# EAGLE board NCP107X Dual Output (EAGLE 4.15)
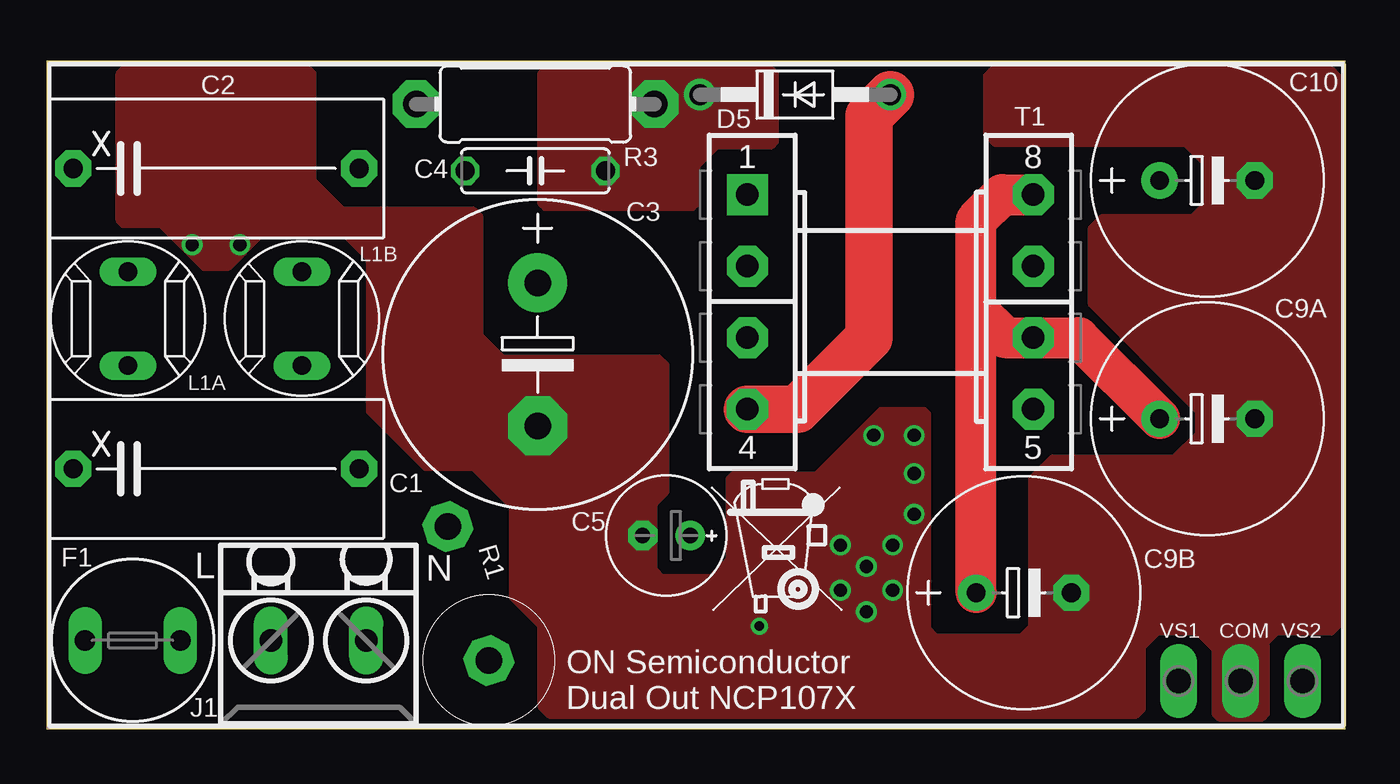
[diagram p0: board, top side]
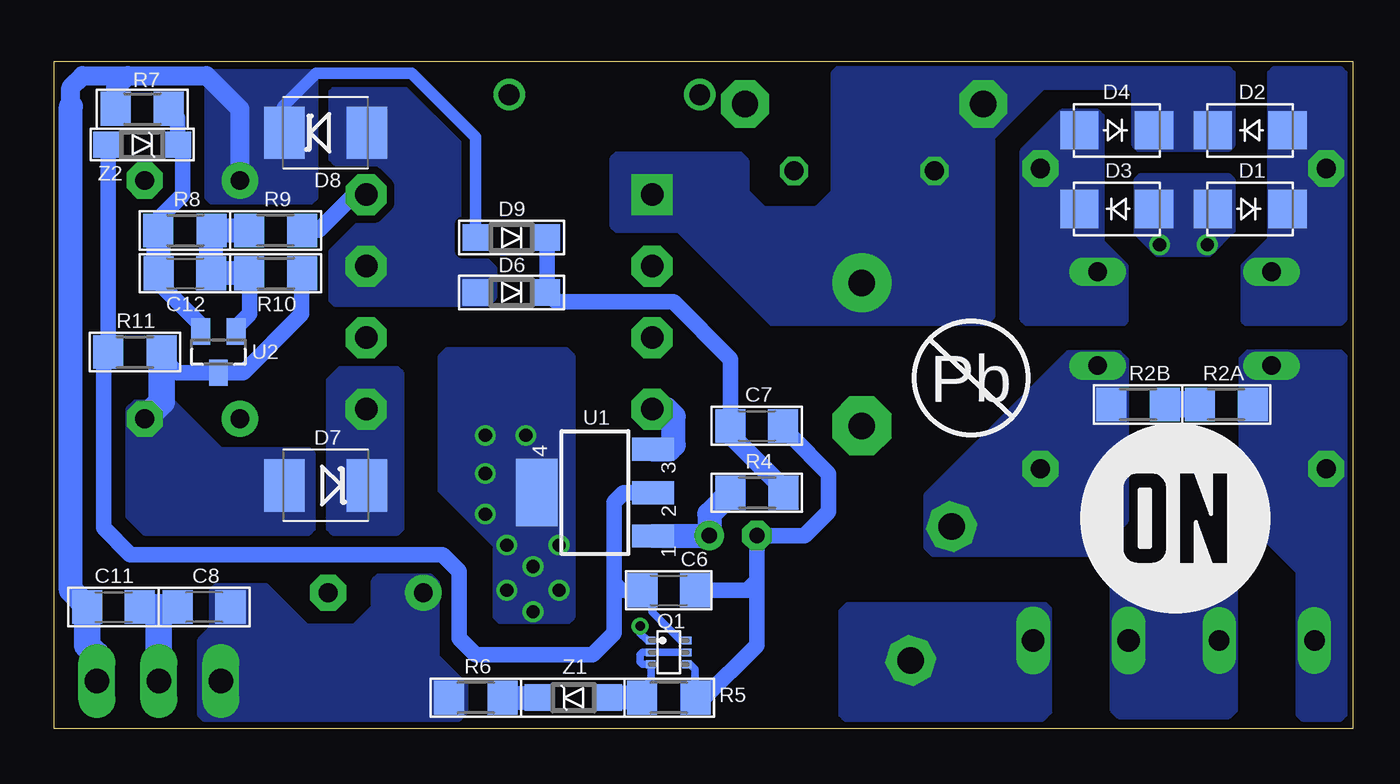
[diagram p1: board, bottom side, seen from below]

Size 69.22 x 35.56 mm. Coordinates in mm from the lower left corner, seen from the top.
Outline: 0,0 69.22,0 69.22,35.56 0,35.56 0,0
Copper layers (1*16): Top 0.035mm / dielectric 1.5mm / Bottom 0.035mm
Design rules "default": minimum track width 10mil, minimum drill 19mil, track to track 8mil, track to pad 8mil, pad to pad 8mil, via to via 8mil, smd to smd 8mil, copper to edge 10mil, drill to drill 8mil, minimum pad ring 10mil, minimum via ring 8mil, stop-mask expansion 4mil, vias tented up to drill 0mil, thermal gap 10mil

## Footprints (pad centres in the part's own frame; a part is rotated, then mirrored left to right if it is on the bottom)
XC18B7.5LS15 = drill 1.016 pad 1.93 octagon: 1 -7.62,0; 2 7.62,0
E7,5-16 = drill 1.4 pad 3.15 round: + -3.81,0 | drill 1.4 pad 3.15 octagon: - 3.81,0
C075-025X080 = drill 1 octagon: 1 -3.74,0; 2 3.74,0
E2.5-6.5 = drill 0.813 pad 1.575 round: + -1.27,0 | drill 0.813 pad 1.575 octagon: - 1.27,0
C1206 = smd 1.6 x 1.8: 1 -1.4,0; 2 1.4,0
E5-12,5 = drill 1 pad 1.93 round: + -2.54,0 | drill 1 pad 1.93 octagon: - 2.54,0
P1-13Y = drill 1.321 pad 1.905 long: 1 0,0
SMA-DIODE = smd 2.032 x 2.032: A 1.994,0; C -1.994,0
DO41-10 = drill 1.118 round: A 5.08,0; C -5.08,0
SOD123 = smd 1.4 x 1.4: A 1.9,0; C -1.9,0
SMB@1 = smd 2.159 x 2.794: A 2.2,0; C -2.2,0
TR5 = drill 1.1 pad 1.778 long: 1 -2.54,0; 2 2.54,0
2-PIN = drill 1.2 long: + -2.54,0; - 2.54,0
WE-7447728215 = drill 1 long: P$1 -2.5,0; P$2 2.5,0
SOT-363/SC-88 = smd 0.508 x 0.406: 1 -0.95,0.635; 2 -0.95,0; 3 -0.95,-0.635; 4 0.95,-0.635; 5 0.95,0; 6 0.95,0.635
3W-STAND-UP = drill 1.4 pad 2.54 octagon: P$1 3.75,0; P$2 -3.71,0
R1206 = smd 1.6 x 1.803: 1 -1.422,0; 2 1.422,0
0411/12 = drill 1.4 pad 2.54 octagon: 1 -6.35,0; 2 6.35,0
E_16/8/5-EF_16-HORIZONTAL = drill 1.2 pad 2.184 square: 1 -7.62,5.715 | drill 1.2 pad 2.184 octagon: 2 -7.62,1.905; 3 -7.62,-1.905; 4 -7.62,-5.715; 5 7.62,-5.715; 6 7.62,-1.905; 7 7.62,1.905; 8 7.62,5.715
SOT-223 = smd 1.219 x 2.235: 1 -2.311,-3.099; 2 0,-3.099; 3 2.311,-3.099 | smd 3.6 x 2.2: 4 0,3.099
SOT-23 = smd 1 x 1.4: 1 -0.95,-1.1; 2 0.95,-1.1; 3 0,1.1

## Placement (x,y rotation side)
C1  100nF  [XC18B7.5LS15]  9.02,13.84 0 top
C2  100nF  [XC18B7.5LS15]  9.02,29.85 0 top
C3  10uF  [E7,5-16]  26.16,19.94 270 top
C4  1nF  [C075-025X080]  26.04,29.72 0 top
C5  22uF  [E2.5-6.5]  33.02,10.29 180 top
C6  1nF  [C1206]  36.45,7.37 0 bottom
C7  0.1uF  [C1206]  31.75,16.13 0 bottom
C8  0.1uF  [C1206]  61.21,6.48 180 bottom
C9A  1500uF  [E5-12,5]  61.85,16.51 0 top
C9B  1500uF  [E5-12,5]  52.07,7.24 0 top
C10  1000uF  [E5-12,5]  61.85,29.21 0 top
C11  0.1uF  [C1206]  66.04,6.48 0 bottom
C12  0.1uF  [C1206]  62.23,24.26 0 bottom
COM  TPPAD1-13Y  [P1-13Y]  63.63,2.54 0 top
D1  MRA4007  [SMA-DIODE]  5.46,27.69 180 bottom
D2  MRA4007  [SMA-DIODE]  5.46,31.88 0 bottom
D3  MRA4007  [SMA-DIODE]  12.57,27.69 0 bottom
D4  MRA4007  [SMA-DIODE]  12.57,31.88 180 bottom
D5  1N4937  [DO41-10]  39.88,33.78 0 top
D6  BAT54  [SOD123]  44.83,23.24 180 bottom
D7  MBRS240  [SMB@1]  54.74,12.95 180 bottom
D8  MBRS240  [SMB@1]  54.74,31.75 0 bottom
D9  MMSD4148A  [SOD123]  44.83,26.16 180 bottom
E$2  [ON2]  9.45,11.21 0 bottom
F1  1A  [TR5]  4.57,4.7 180 top
J1  [2-PIN]  14.48,4.7 0 top
L1A  1mH  [WE-7447728215]  4.32,21.84 90 top
L1B  1mH  [WE-7447728215]  13.59,21.84 90 top
Q1  NST45011  [SOT-363/SC-88]  36.45,4.06 0 bottom
R1  6.5R/2W  [3W-STAND-UP]  22.47,7.18 107 top
R2A  3.3M  [R1206]  6.73,17.27 0 bottom
R2B  3.3M  [R1206]  11.43,17.27 0 bottom
R3  68K  [0411/12]  26.04,33.27 180 top
R4  TBD  [R1206]  31.75,12.57 180 bottom
R5  680  [R1206]  36.45,1.65 0 bottom
R6  10  [R1206]  46.74,1.65 0 bottom
R7  10K  [R1206]  64.52,33.02 180 bottom
R8  1M  [R1206]  62.23,26.54 180 bottom
R9  10K  [R1206]  57.4,26.54 0 bottom
R10  10K  [R1206]  57.4,24.26 180 bottom
R11  4.7K  [R1206]  64.9,20.07 180 bottom
T1  [E_16/8/5-EF_16-HORIZONTAL]  44.96,22.73 0 top
U1  NCP1075  [SOT-223]  40.39,12.57 90 bottom
U2  NCP431A  [SOT-23]  60.45,20.07 180 bottom
U$3  [WEEE_SMALL]  39.04,7.53 0 top
VS1  TPPAD1-13Y  [P1-13Y]  60.33,2.54 0 top
VS2  TPPAD1-13Y  [P1-13Y]  66.93,2.54 0 top
Z1  MMSZ5229B  [SOD123]  41.53,1.65 0 bottom
Z2  MMSZ5223B  [SOD123]  64.52,31.12 180 bottom

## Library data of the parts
C1-C8 C9A C9B C10-C12 R2A R2B R3-R11 = rcl
COM VS1 VS2 = testpad
D1-D9 Z1 Z2 = diode
E$2 = loga
F1 = fuse
J1 = My CONNECTOR lib
L1A L1B = MY  INDUCTOR Lib
Q1 = transistor
R1 = resistor-power
T1 = My X-former
U1 U2 = My IC Lib
U$3 = My Sign Lib

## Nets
N$1: F1.1 J1.+
N$2: J1.- R1.P$2
N$3: C3.- C5.- C6.2 C7.2 C8.2 C9A.- C9B.- C10.- C11.2 COM.1 D1.A D3.A D7.A Q1.1 Q1.4 R5.2 R10.1 R11.1 U1.4 U2.3
N$4: C1.1 F1.2 L1A.P$1 R2A.2
N$5: C1.2 L1B.P$1 R1.P$1 R2B.1
N$6: C4.2 D5.C R3.1
N$7: C2.2 D3.C D4.A L1B.P$2
N$8: R2A.1 R2B.2
N$9: D5.A T1.4 U1.3
N$10: C5.+ R4.2 U1.1
N$11: R6.2 Z1.C
N$12: C2.1 D1.C D2.A L1A.P$2
N$13: C6.1 Q1.6 R11.2 U1.2 Z2.A
N$14: C10.+ C11.1 D8.C D9.A R7.2 VS2.1
N$15: C12.1 R7.1 R8.2 U2.2 Z2.C
N$16: C7.1 D6.C D9.C R4.1
N$17: C3.+ C4.1 D2.C D4.C R3.2 T1.1
N$18: C8.1 C9A.+ C9B.+ R6.1 R9.2 T1.6 T1.8 VS1.1
N$19: D7.C T1.5
N$20: D6.A D8.A T1.7
N$24: C12.2 R8.1 R9.1 R10.2 U2.1
N$25: Q1.2 Q1.3 Q1.5 R5.1 Z1.A

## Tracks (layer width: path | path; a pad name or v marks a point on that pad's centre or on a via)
N$1
  pour Bottom (no thermals): 6.22,6.22 6.22,7.37 6.48,7.62 12.7,7.62 12.83,7.49 12.83,1.02 12.45,0.64 6.6,0.64 6.22,1.02
N$2
  pour Bottom (no thermals): 16.13,0.89 16.13,6.35 16.38,6.6 26.92,6.6 27.31,6.22 27.31,0.76 27.05,0.51 16.51,0.51
N$3  (via drill 0.5, 0.7)
  Bottom 0.406: Q1.4 35.31,3.43 35.05,3.18 35.05,1.65 R5.2 | Q1.1 37.59,4.7 37.97,5.08 v37.97,5.46
  Bottom 0.61: R11.1 63.5,20.07
  Bottom 0.813: C7.2 29.97,16.13 29.97,15.62 27.94,13.59 27.94,11.56 29.21,10.29 C5.- 31.75,7.87 | R5.2 34.8,1.65 34.67,1.52 31.75,4.45 31.75,7.87 | C6.2 32.26,7.37 31.75,7.87 | 63.48,19.56 63.25,19.56 62.65,18.97 U2.3 59.14,18.97 56.01,22.1 56.01,24.26 R10.1
  Bottom 1.422: R11.1 63.48,19.56 63.48,17.42 C9A.- | 63.63,6.48 C8.2 | 63.63,6.48 C11.2 | COM.1 63.63,6.48
  other vias: 7.75,25.78 10.29,25.78 44.07,15.62 46.23,15.62 46.23,13.59 46.23,11.43 45.09,9.78 45.09,7.37 43.69,8.64 42.29,7.37 42.29,9.78 43.69,6.22
  pour Bottom (no thermals): 6.6,29.46 11.3,29.46 11.56,29.21 11.56,26.42 10.41,25.27 7.62,25.27 6.35,26.54 6.35,29.21
  pour Bottom (no thermals): 55.37,10.67 55.37,14.61 55.63,14.86 60.33,14.86 62.87,17.4 64.9,17.4 65.28,17.02 65.28,11.3 64.39,10.41 55.63,10.41
  pour Top (no thermals): 9.65,24.51 8.38,24.51 6.1,26.8 4.06,26.8 3.81,27.05 3.81,34.93 4.06,35.18 13.97,35.18 14.22,34.93 14.22,29.21 15.75,27.69 22.73,27.69 23.11,27.31 23.11,20.96 24.26,19.81 32.64,19.81 33.02,19.43 33.02,12.57 32.39,11.94 32.39,8.51 32.77,8.13 35.43,8.13 36.32,9.02 36.32,13.34 36.58,13.59 41.02,13.59 44.45,17.02 46.74,17.02 46.99,16.76 46.99,5.33 47.37,4.95 51.94,4.95 52.45,5.46 52.45,13.34 53.59,14.48 60.07,14.48 61.34,15.75 61.34,16.89 55.63,22.61 55.63,26.67 56.26,27.31 61.09,27.31 61.72,27.94 61.72,30.1 60.71,31.12 50.55,31.12 50.04,31.62 50.04,34.8 50.42,35.18 68.45,35.18 68.83,34.8 68.83,5.46 68.45,5.08 65.53,5.08 65.02,4.57 65.02,0.76 64.77,0.51 62.48,0.51 62.23,0.76 62.23,4.19 61.34,5.08 59.18,5.08 58.42,4.32 58.42,1.02 58.04,0.64 26.8,0.64 26.29,1.14 26.29,5.46 24.77,6.99 24.77,11.81 22.73,13.84 20.19,13.84 17.15,16.89 17.15,25.02 15.88,26.29 11.43,26.29
  pour Bottom (no thermals): 41.53,5.97 41.53,19.81 41.91,20.19 48.26,20.19 48.64,19.81 48.64,12.7 45.72,9.78 45.72,5.97 45.47,5.72 41.78,5.72
N$4
  pour Bottom (no thermals): 0.38,0.76 0.38,19.81 0.64,20.07 5.59,20.07 5.97,19.69 5.97,11.43 2.92,8.38 2.92,0.76 2.67,0.51 0.64,0.51
N$5
  pour Bottom (no thermals): 12.07,19.69 12.07,11.05 13.84,9.27 22.35,9.27 22.73,9.65 22.73,12.45 15.11,20.07 12.45,20.07
N$6
  pour Top (no thermals): 34.42,27.69 26.54,27.69 26.29,27.94 26.29,34.93 26.54,35.18 38.61,35.18 38.86,34.93 38.86,31.24 38.61,30.99 35.69,30.99 34.67,29.97 34.67,27.94
N$7
  pour Bottom (no thermals): 15.49,32.89 17.65,30.73 17.65,21.84 17.4,21.59 12.19,21.59 12.07,21.72 12.07,24.64 13.34,25.91 13.34,32.64 13.59,32.89
N$8
  Bottom 1.422: 10.03,17.27 R2B.2 R2A.1
N$9
  Top 2.54: D5.A 43.82,32.64 43.82,20.83 40.01,17.02 T1.4
  Bottom 1.27: U1.3 36.42,14.88 36.2,15.11 36.2,16.64 36.58,17.02 T1.4
N$10
  Bottom 1.016: R4.2 33.15,12.57
  Bottom 1.27: 33.15,12.57 34.29,11.43 C5.+ 34.32,10.26 U1.1
N$11
  Bottom 1.27: 45.34,1.65 R6.2 Z1.C
N$12
  pour Bottom (no thermals): 0.38,21.84 0.38,34.93 0.64,35.18 4.19,35.18 4.45,34.93 4.45,26.04 5.84,24.64 5.84,21.72 5.72,21.59 0.64,21.59
N$13
  Bottom 0.406: Q1.6 35.81,4.7 37.34,6.22 37.34,6.86 C6.1
  Bottom 0.813: U1.2 38.86,12.57 39.37,12.07 39.37,7.75 | 39.37,7.75 39.37,5.08 40.51,3.94 46.74,3.94 47.63,4.83 47.63,8.38 48.51,9.27 65.15,9.27 66.57,10.69 66.57,19.79 66.29,20.07 R11.2 66.32,31.01 Z2.A | C6.1 38.99,7.37 39.37,7.75
N$14
  Bottom 0.61: D8.C 57.02,31.75 57.02,33.15 55.25,34.93 50.17,34.93 46.74,31.5 D9.A
  Bottom 1.016: 68.33,33.15 68.33,34.16 67.69,34.8 65.28,34.8 | 65.28,34.8 61.09,34.8 59.31,33.02 C10.+ | R7.2 65.94,34.14 65.28,34.8
  Bottom 1.27: 68.33,33.15 68.33,7.37 C11.1
  Bottom 1.422: VS2.1 66.93,3.94 67.44,4.45 C11.1
  pour Bottom (isolate 0.406, no thermals): 60.83,28.07 55.5,28.07 55.25,28.32 55.25,34.93 55.5,35.18 60.83,35.18 61.09,34.93 61.09,28.32
N$15
  Bottom 0.813: R8.2 63.63,26.54 63.63,27.18 62.36,28.44 62.36,30.87 Z2.C 62.62,32.52 63.12,33.02 R7.1 | C12.1 63.63,23.75 61.4,21.52 U2.2
  Bottom 1.27: R8.2 63.65,26.44 63.63,26.42 63.63,26.41 C12.1
N$16
  Bottom 0.813: C7.1 33.15,19.69 36.2,22.73 42.42,22.73 D6.C D9.C
  Bottom 1.016: R4.1 30.33,12.8 33.15,15.62 C7.1
N$17
  pour Bottom (no thermals): 6.35,31.12 6.35,34.93 6.6,35.18 27.43,35.18 27.69,34.93 27.69,28.58 28.58,27.69 31.37,27.69 32.26,28.58 32.26,30.23 32.64,30.61 39.24,30.61 39.5,30.35 39.5,26.8 39.24,26.54 35.94,26.54 30.99,21.59 19.56,21.59 19.18,21.97 19.18,31.5 16.51,34.16 11.94,34.16 11.68,33.91 11.68,31.12 11.43,30.86 6.6,30.86
N$18
  Top 2.184: T1.8 50.93,28.45 49.53,27.05 49.53,22.35 | C9B.+ 49.53,22.35 | 49.53,22.35 51.05,20.83 T1.6 54.99,20.83 C9A.+
  Bottom 0.813: R9.2 55.12,26.54 53.21,28.45 T1.8
  pour Bottom (no thermals): 47.24,0.89 47.24,2.29 48.77,3.81 48.77,7.75 49.15,8.13 51.94,8.13 52.2,7.87 52.2,6.48 53.21,5.46 55.75,5.46 57.91,7.62 60.58,7.62 60.83,7.37 60.83,5.33 61.47,4.7 61.47,0.76 61.21,0.51 47.63,0.51
N$19
  pour Bottom (no thermals): 50.67,10.67 50.67,18.92 50.93,19.18 53.98,19.18 54.61,18.54 54.61,10.67 54.36,10.41 50.93,10.41
N$20
  pour Bottom (isolate 0.406, no thermals): 54.23,22.61 46.1,22.61 45.72,22.99 45.72,24.51 47.63,26.42 47.63,31.24 50.55,34.16 54.23,34.16 54.48,33.91 54.48,30.35 54.23,30.1 51.94,30.1 51.05,29.21 51.05,27.69 51.82,26.92 52.96,26.92 54.48,25.4 54.48,22.86
N$24
  Bottom 0.61: 58.8,24.26 R10.2
  Bottom 0.813: U2.1 59.5,21.4 58.8,22.1 58.8,24.26
  Bottom 1.27: C12.2 | R10.2 C12.2 | C12.2 60.83,26.54 R8.1 R9.1 58.8,26.54
N$25
  Bottom 0.406: R5.1 37.85,1.65 37.85,2.16 37.4,2.61 Q1.3 37.85,3.43 37.97,3.56 37.97,3.94 37.85,4.06 Q1.2 Q1.5
  Bottom 1.27: R5.1 Z1.A

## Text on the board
tPlace: L | N | ON Semiconductor | Dual Out NCP107X
bPlace: Pb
